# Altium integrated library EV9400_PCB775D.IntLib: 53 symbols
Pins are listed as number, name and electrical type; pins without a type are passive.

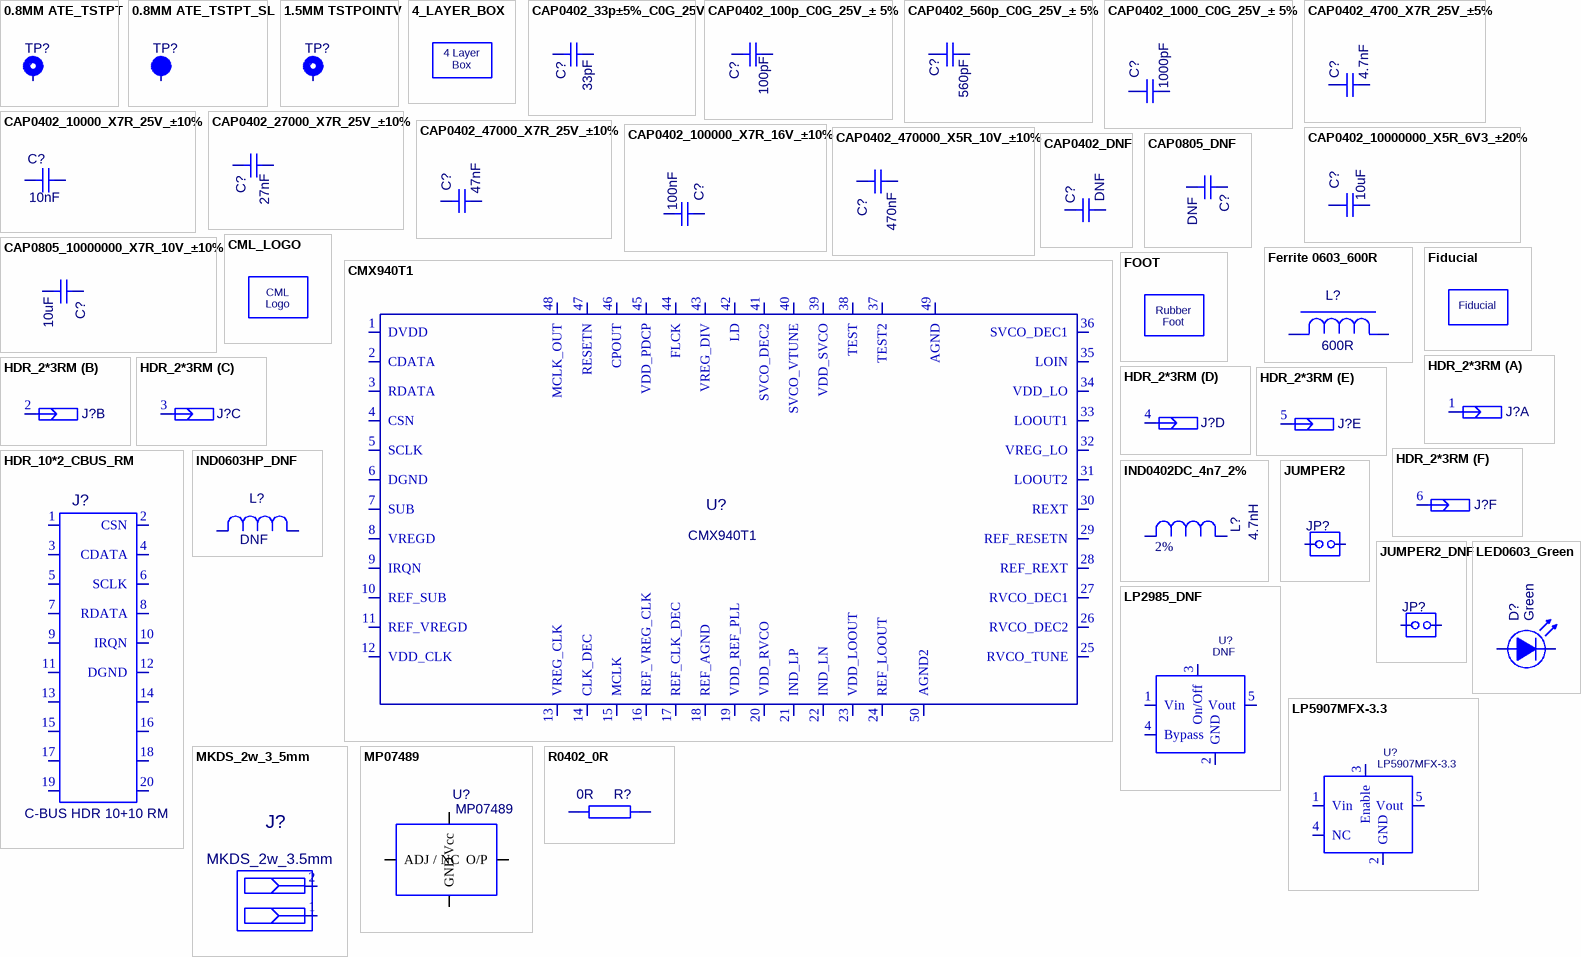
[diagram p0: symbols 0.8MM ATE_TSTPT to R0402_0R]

## 0.8MM ATE_TSTPT
designator TP?, comment VREG_DIV  (value not drawn)  (no BOM)
0.8mm pad 0.3mm via, 1.27mm spacing circle; WhenFit: DNF; Checked: no; Value: PCB Pad
footprint 0.8MM_ATE_TSTPT (0.8mm pad 0.3mm via, 1.27mm spacing circle)
pins: 1 0

## 0.8MM ATE_TSTPT_SL
designator TP?, comment REXT  (value not drawn)  (no BOM)
0.8mm pad top only, 1.27mm spacing circle; Value: PCB Pad; WhenFit: DNF; Checked: no
footprint 0.8MM ATETSTPT-SL (0.8mm pad on top layer 1.27mm spacing circle)
pins: 1 0

## 1.5MM TSTPOINTV
designator TP?, comment +V  (value not drawn)  (no BOM)
1.5mm Testpoint with via; Value: PCB Pad; WhenFit: DNF; Checked: no
footprint 1.5MM TSTPOINTV (1.5mm testpoint with 0.3mm via)
pins: 1 0

## 4_LAYER_BOX
designator LAY?  (value not drawn)  (no BOM)
Checked: no; Value: 4 Layer PCB
footprint 4_LAYER_BOX

## CAP0402_33p±5%_C0G_25V
designator C?, comment 33pF
0402 Cer. Cap. 33pF±5% 25V C0G; Part Number: CAP199; WhenFit: SMT Cap; Checked: no; Dielectric: C0G/NP0; ExpValue: 33; Tolerance: 5%; ExpValUnit: pF
footprint 0402COM
pins: 1, 2

## CAP0402_100p_C0G_25V_± 5%
designator C?, comment 100pF
0402 Cer. Cap. 100pF±5% 25V C0G; Part Number: CAP205; WhenFit: SMT Cap; Checked: no; Dielectric: C0G/NP0; ExpValue: 100; TGMC P/N: 201-1000; Tolerance: 5%; ExpValUnit: pF
footprint 0402COM
pins: 1, 2

## CAP0402_560p_C0G_25V_± 5%
designator C?, comment 560pF
0402 Cer. Cap. 560pF±5% 25V C0G; Part Number: CAP216; WhenFit: SMT Cap; Checked: no; Dielectric: C0G/NP0; ExpValue: 560; Tolerance: 5%; ExpValUnit: pF
footprint 0402COM
pins: 1, 2

## CAP0402_1000_C0G_25V_± 5%
designator C?, comment 1000pF
0402 Cer. Cap. 1000pF±5% 25V C0G; Part Number: CAP219; WhenFit: SMT Cap; Checked: no; Dielectric: C0G/NP0; ExpValue: 1000; Tolerance: 5%; ExpValUnit: pF
footprint 0402COM
pins: 1, 2

## CAP0402_4700_X7R_25V_±5%
designator C?, comment 4.7nF
0402 Cer. Cap. 4.7nF 25V X7R ±5%; Part Number: CAP274; WhenFit: SMT Cap; Checked: no; ExpValue: 4700; ExpValUnit: pF
footprint 0402COM
pins: 1, 2

## CAP0402_10000_X7R_25V_±10%
designator C?, comment 10nF
0402 Cer. Cap. 10nF 25V X7R ±10%; Part Number: CAP228; WhenFit: SMT Cap; Checked: no; ExpValue: 10000; TGMC P/N: 201-1002; ExpValUnit: pF
footprint 0402COM
pins: 1, 2

## CAP0402_27000_X7R_25V_±10%
designator C?, comment 27nF
0402 Cer. Cap. 27nF 25V X7R ±10%; Part Number: CAP231; WhenFit: SMT Cap; Checked: no; ExpValue: 27000; ExpValUnit: pF
footprint 0402COM
pins: 1, 2

## CAP0402_47000_X7R_25V_±10%
designator C?, comment 47nF
0402 Cer. Cap. 47nF 25V X7R ±10%; Part Number: CAP234; WhenFit: SMT Cap; Checked: no; ExpValue: 47000; TGMC P/N: 201-4702X; ExpValUnit: pF
footprint 0402COM
pins: 1, 2

## CAP0402_100000_X7R_16V_±10%
designator C?, comment 100nF
0402 Cer. Cap. 100nF 16V X7R ±10%; Part Number: CAP237; WhenFit: SMT Cap; Checked: no; ExpValue: 100000; ExpValUnit: pF
footprint 0402COM
pins: 1, 2

## CAP0402_470000_X5R_10V_±10%
designator C?, comment 470nF
0402 Cer. Cap. 470nF 10V X5R ±10%; Part Number: CAP240; WhenFit: SMT Cap; Checked: no; ExpValue: 470000; ExpValUnit: pF
footprint 0402COM
pins: 1, 2

## CAP0402_10000000_X5R_6V3_±20%
designator C?, comment 10uF
0402 Cer. Cap. 10uF 6V3 X5R ±20%; Part Number: CAP244; WhenFit: SMT Cap; Checked: no; ExpValue: 10000000; ExpValUnit: pF
footprint 0402COM
pins: 1, 2

## CAP0402_DNF
designator C?, comment DNF
Pads for 0402 Ceramic Capacitor; WhenFit: DNF; Checked: no; ExpValue: PCB Pads
footprint 0402COM
pins: 1, 2

## CAP0805_10000000_X7R_10V_±10%
designator C?, comment 10uF
0805 Cer. Cap. 10uF±10% 10V X7R; Part Number: CAP262; WhenFit: SMT Capacitor; Checked: no; TGMC P/N: MML203-1005; ExpValue: 10000000; Tolerance: 10%; ExpValUnit: pF
footprint 0805COM
pins: 1, 2

## CAP0805_DNF
designator C?, comment DNF
Unused pads for 0805 Ceramic Capacitor; WhenFit: DNF; Checked: no; ExpValue: PCB Pads
footprint 0805COM
pins: 1, 2

## CML_LOGO
designator LOGO?  (value not drawn)  (no BOM)
footprint CML_LOGO

## CMX940T1
designator U?
CMX940T1, High Performance Synthesizer; WhenFit: SMT Other; Checked: no
footprint QFN50P700X700X110_HS-50N (QFN, 48-Leads, Body 7.00x7.00mm, Pitch 0.50mm, Split Thermal Pad, IPC MedDensity)
pins: 1 DVDD (power) "+3V3 supply for digital logic", 2 CDATA (in) "C-BUS serial data input from µC", 3 RDATA (out) "3-state C-BUS serial data output to µC", 4 CSN (in) "Chip Select. Active low", 5 SCLK (in) "C-BUS serial clock input from the µC.", 6 DGND "Master clock input (10MHz - 40MHz).", 7 SUB "Digital logic substrate. Should be connected to DVSS. (D2)", 8 VREGD "An internally generated 1.8V supply, 100nF external", 9 IRQN (out) "A ‘wire-ORable’ output for connection to the host µC's Interrupt Request input", 10 REF_SUB "Digital logic substrate. Connect to DVSS. (D1)", 11 REF_VREGD "An internally generated 1.8V supply, 100nF external", 12 VDD_CLK (power) "+3V3 supply for the MCLK voltage regulator.", 13 VREG_CLK "An internally generated 1.8V supply, 470nF external", 14 CLK_DEC "MCLK voltage regulator filter, 4n7 external", 15 MCLK (in) "Master clock input (10MHz - 40MHz).", 16 REF_VREG_CLK "Internally generated 1.8V supply, 470nF external", 17 REF_CLK_DEC "MCLK voltage regulator filter, 4n7 external", 18 REF_AGND "RPLL 1.8V return ground", 19 VDD_REF_PLL (power) "+3V3 supply for Reference PLL", 20 VDD_RVCO (power) "+3V3 supply for Reference VCO", 21 IND_LP "Reference VCO inductor +ve terminal.", 22 IND_LN "Reference VCO inductor -ve terminal.", 23 VDD_LOOUT (power) "LO buffer +3V3 supply", 24 REF_LOOUT (out) "Local oscillator output  for transmission.", 25 RVCO_TUNE (out) "Reference VCO tune voltage output (test-point only).", 26 RVCO_DEC2 "Reference VCO decoupling pin2", 27 RVCO_DEC1 "Reference VCO decoupling pin1", 28 REF_REXT "External 47.5kO bias resistor connected to AVSS.", 29 REF_RESETN (in) "Chip enable active high 3V  (D1)", 30 REXT "External 47.5kO bias resistor connected to AVSS.", 31 LOOUT2 (out) "Local oscillator output  for reception.", 32 VREG_LO "An internally generated 1.8V supply, 100nF external", 33 LOOUT1 (out) "Local oscillator output  for transmission.", 34 VDD_LO (power) "Positive 3V3 supply for Lout RX TX buffer", 35 LOIN (in) "External local oscillator RF input", 36 SVCO_DEC1 "SVCO  decoupling pin1, 470nF external", 37 TEST2 (in) "Master clock input (10MHz - 120MHz).", 38 TEST (out) "RVCO amplitude test output", 39 VDD_SVCO "SVCO +3V3 supply", 40 SVCO_VTUNE (in) "Synthesiser VCO tune voltage input .", 41 SVCO_DEC2 "SVCO  decoupling pin2, 470nF external", 42 LD (out) "Chip general test output and Lock Detect (LD)", 43 VREG_DIV "Synth Ndivider 1.8V, 100nF external", 44 FLCK (out) "Synth phase detector VDD18 test output and FLCK", 45 VDD_PDCP (power) "Synth phase detector and charge pump +3V3 supply", 46 CPOUT (out) "Synth charge pump out", 47 RESETN (in) "Chip enable active high 3V (D2)", 48 MCLK_OUT (out) "Chip general test output, MCLK_Out", 49 AGND, 50 AGND2

## Ferrite 0603_600R
designator L?, comment 600R
Ferrite, 0603, 600R @ 100MHz 1.3A; Part Number: TRF089; WhenFit: SMT Other; Checked: no; ExpValue: 600; TGMC P/N: ATL300-0001
footprint 0603COM
pins: 1, 2

## Fiducial
designator FID?  (value not drawn)  (no BOM)
1.5mm round pad Fiducial; Checked: no
footprint 1.5MM Fiducial (1.5mm disc in copper, 3mm disk in mask)

## FOOT
designator FOOT?, comment Foot  (value not drawn)
12.7mm square stick-on foot; Part Number: FIX006; WhenFit: After Wash
footprint FOOT

## HDR_2*3RM
designator J?  (value not drawn)
3+3 double row 0.1in header right angle; Part Number: CON082; Manuf P/N: TSW-103-08-G-D-RA; WhenFit: PTH; Checked: no
footprint IDC6RM
part A pins: 1
part B pins: 2
part C pins: 3
part D pins: 4
part E pins: 5
part F pins: 6

## HDR_10*2_CBUS_RM
designator J?, comment C-BUS HDR 10+10 RM
C-BUS R/A Male Header; Part Number: CON057; WhenFit: PTH; Checked: no
footprint IDC20RM
pins: 1, 2 CSN, 3, 4 CDATA, 5, 6 SCLK, 7, 8 RDATA, 9, 10 IRQN, 11 DGND, 12 DGND, 13, 14, 15, 16, 17, 18, 19, 20

## IND0402DC_4n7_2%
designator L?, comment 4.7nH  Tolerance: 2%
0402 inductor, 4.7nH, 0402DC-4N7XGR; Part Number: TRF146; WhenFit: SMT Inductor; Checked: no; ExpValue: 4.7; ExpValUnit: nH
footprint 0402COM
pins: 1, 2

## IND0603HP_DNF
designator L?, comment DNF
Pads for Coilcraft 0603 Inductor; WhenFit: SMT Inductor; Checked: no; ExpValue: PCB Pads; ExpValUnit: nH
footprint 0603COM
pins: 1, 2

## JUMPER2
designator JP?, comment Jumper2  (value not drawn)
Pin header 2X1; Part Number: CON005; WhenFit: PTH; Checked: no; SignalName: {SignalName}
footprint JMP2
pins: 1, 2

## JUMPER2_DNF
designator JP?, comment DNF  (value not drawn)  (no BOM)
Holes for Pin header 2X1; WhenFit: DNF; Checked: no
footprint JMP2
pins: 1, 2

## LED0603_Green
designator D?, comment Green
Green 0603 LED, KPT-1608CGCK; Part Number: OPT011; WhenFit: SMT Other; Checked: no
footprint LED0603
pins: 1 Anode, 2 Cathode

## LP2985_DNF
designator U?, comment DNF  (no BOM)
Pads for LP2985 regulator, SOT23-5; WhenFit: DNF; Checked: no
footprint SOT23-5
pins: 1 Vin (power), 2 GND (power), 3 On/Off (in), 4 Bypass, 5 Vout (power)

## LP5907MFX-3.3
designator U?
LP5907MFX-3.3,   3.3V, 250mA ULN Low-IQ LDO Regulator, SOT23-5; Part Number: ICS165; WhenFit: SMT Other; Checked: no; Marking: LLVB; Alternative: 595-LP5907QMFX-3.3Q1  (RAHQ)
footprint SOT23-5
pins: 1 Vin (power), 2 GND (power), 3 Enable (in), 4 NC, 5 Vout (power)

## MKDS_2w_3_5mm
designator J?, comment MKDS_2w_3.5mm
2-WAY PCB screw terminal block - MKDS 1/ 2-3,5 HT BK; Part Number: CON126; Manuf P/N: 1985807; WhenFit: After Wash; Checked: no
footprint MKDS_2 (2-way screw terminal block, 3.5mm pitch)
pins: 1 (io), 2 (io)

## MP07489
designator U?
38.40MHz GTXO-74V/JI SM Sine VCTCXO 2.5ppm; Part Number: XTL041; WhenFit: SMT Other
footprint GTXO-74 (QFN, 4-Leads, Body 7.03x5.03mm , IPC Medium Density)
pins: 1 ADJ / NC "NC or for frequency adjustment", 2 GND, 3 O/P (out), 4 Vcc

## R0402_0R
designator R?, comment 0R
Resistor 0402 0R 0.063W; Part Number: RES199; WhenFit: SMT Resistor; Checked: no; ExpValue: 0; ExpValUnit: Ohm
footprint 0402COM
pins: 1, 2

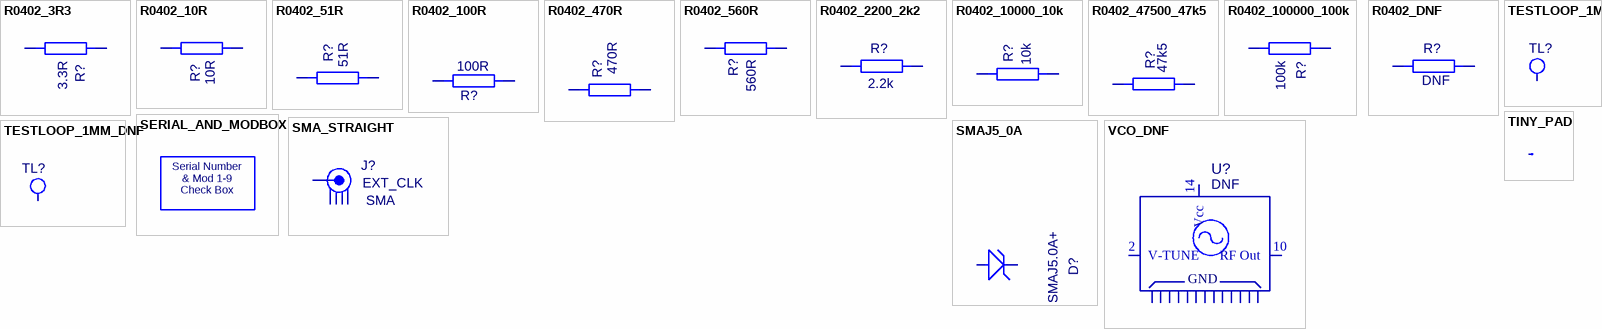
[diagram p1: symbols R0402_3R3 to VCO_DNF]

## R0402_3R3
designator R?, comment 3.3R
Resistor 0402 3.3R 1% 0.063W   ( 51Y ); Part Number: RES212; WhenFit: SMT Resistor; Checked: no; ExpValue: 3.3; TGMC P/N: 101-0033; ExpValUnit: Ohm
footprint 0402COM
pins: 1, 2

## R0402_10R
designator R?, comment 10R
Resistor 0402 10R 1% 0.063W   ( 01X ); Part Number: RES224; WhenFit: SMT Resistor; Checked: no; ExpValue: 10; TGMC P/N: 101-0100; ExpValUnit: Ohm
footprint 0402COM
pins: 1, 2

## R0402_51R
designator R?, comment 51R
Resistor 0402 51R 1% 0.063W  ( 69X = 51.1R ); Part Number: RES241; WhenFit: SMT Resistor; Checked: no; ExpValue: 51; ExpValUnit: Ohm
footprint 0402COM
pins: 1, 2

## R0402_100R
designator R?, comment 100R
Resistor 0402 100R 1% 0.063W  ( 01A ); Part Number: RES248; WhenFit: SMT Resistor; Checked: no; ExpValue: 100; ExpValUnit: Ohm
footprint 0402COM
pins: 1, 2

## R0402_470R
designator R?, comment 470R
Resistor 0402 470R 1% 0.063W  ( 66A = 475R ); Part Number: RES265; WhenFit: SMT Resistor; Checked: no; ExpValue: 470; TGMC P/N: 101-4700; ExpValUnit: Ohm
footprint 0402COM
pins: 1, 2

## R0402_560R
designator R?, comment 560R
Resistor 0402 560R 1% 0.063W  ( 73A = 562R ); Part Number: RES267; WhenFit: SMT Resistor; Checked: no; ExpValue: 560; TGMC P/N: 101-5600; ExpValUnit: Ohm
footprint 0402COM
pins: 1, 2

## R0402_2200_2k2
designator R?, comment 2.2k
Resistor 0402 2.2k 1% 0.063W  (34B = 2.21k ); Part Number: RES281; WhenFit: SMT Resistor; Checked: no; ExpValue: 2200; ExpValUnit: Ohm
footprint 0402COM
pins: 1, 2

## R0402_10000_10k
designator R?, comment 10k
Resistor 0402 10k 1% 0.063W  ( 01C ); Part Number: RES297; WhenFit: SMT Resistor; Checked: no; ExpValue: 10000; TGMC P/N: 101-1002; ExpValUnit: Ohm
footprint 0402COM
pins: 1, 2

## R0402_47500_47k5
designator R?, comment 47k5
Resistor 0402 47k5 1% 0.063W  ( 66C = 47.5k ); Part Number: RES314; WhenFit: SMT Resistor; Checked: no; ExpValue: 47500; ExpValUnit: Ohm
footprint 0402COM
pins: 1, 2

## R0402_100000_100k
designator R?, comment 100k
Resistor 0402 100k 1% 0.063W  ( O1D ); Part Number: RES322; WhenFit: SMT Resistor; Checked: no; ExpValue: 100000; TGMC P/N: 101-1003; ExpValUnit: Ohm
footprint 0402COM
pins: 1, 2

## R0402_DNF
designator R?, comment DNF
Pads for Resistor 0402; WhenFit: DNF; Checked: no; ExpValue: PCB Pads; ExpValUnit: Tx/Rx
footprint 0402COM
pins: 1, 2

## SERIAL_AND_MODBOX
designator MODBO?, comment 8 Mod Box  (value not drawn)  (no BOM)
SERIAL_AND_MODBOX
footprint SERIAL_AND_MOD

## SMA_STRAIGHT
designator J?, comment SMA  SignalName: EXT_CLK
PCB Mounted SMA Socket (Upright); Part Number: CON046; Manuf P/N: 5-1814832-1; WhenFit: PTH; Checked: no
footprint SMA
pins: 1 SIG (io), 2 GND (power), 3 GND (power), 4 GND (power), 5 GND (power)

## SMAJ5_0A
designator D?, comment SMAJ5.0A+
5V Transient Suppression Diode, DO-214AC; Part Number: DSM083; WhenFit: SMT Other; Checked: no
footprint DO-214AC SMA
pins: 1 K, 2 A

## TESTLOOP_1MM
designator TL?, comment 1.5mm testloop (Y)  (value not drawn)
Yellow 1.5mm testloop (1.0 mm hole); Part Number: CON108; WhenFit: PTH; Checked: no; SignalName: AGND
footprint TESTLOOP_1.0MM
pins: 1

## TESTLOOP_1MM_DNF
designator TL?, comment DNF  (value not drawn)  (no BOM)
1mm hole  for 1.5mm testloop e.g. Rapid  17-1819; WhenFit: PTH; Checked: no; SignalName: MCLK_OUT
footprint TESTLOOP_1.0MM
pins: 1

## TINY_PAD
designator P?, comment PCB Pad  (value not drawn)  (no BOM)
Very Small Pad - used to remove all of the 'unconnected pin' errors from ERC & DRC; Checked: no; SignalName: {SignalName}
footprint TINYPAD
pins: 1 0

## VCO_DNF
designator U?, comment DNF  (no BOM)
Pads for 0.5in VCO module; WhenFit: DNF; Checked: No
footprint PL-012 (SM VCO 0.5in square Mini-circuits case CK605)
pins: 1 GND, 2 V-TUNE, 3 GND, 4 GND, 5 GND, 6 GND, 7 GND, 8 GND, 9 GND, 10 RF Out (out), 11 GND, 12 GND, 13 GND, 14 Vcc (power), 15 GND, 16 GND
